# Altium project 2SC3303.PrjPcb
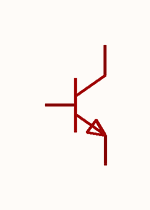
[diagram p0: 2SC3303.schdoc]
1 sheet, 1 parts. Net scope: global (net labels, ports and power ports of the same name join across sheets).

## Sheet 2SC3303.schdoc
size 127 x 101 mm

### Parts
Q?  2sc3303(range:120-240)  [TO-252-2_L6.5-W6.1-P4.58-LS10.0-TL]  (value not drawn)

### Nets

Not connected (* = marked no-connect by the designer): Q? 1(B) 3(E) 4(C)

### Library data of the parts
Q? = 2sc3303(range:120-240): 晶体管类型:NPN;集电极电流(Ic):5A;集射极击穿电压(Vceo):80V;耗散功率(Pd):1W;直流电流增益(hFE):120;; Manufacturer: CJ(江苏长电/长晶); AddInBom: yes; ModelId: 6b2ea0154a284e6db98f69bccdba3606; ModelName: TO-252-2_L6.5-W6.1-H2.3-LS10.0-P4.58; ModelTransform: 255.905,390.52442,0,270,0,0,38.183,0.432,0; type: NPN; Current - Collector(Ic): 5A; Collector - Emitter Voltage VCEO: 80V; Pd - Power Dissipation: 1W; DC Current Gain: 120; Transition frequency(fT): 20MHz; Current - Collector Cutoff: 1uA; Vce Saturation(VCE(sat)): 400mV; Emitter-Base Voltage(Vebo): 7V; Number: 1个NPN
